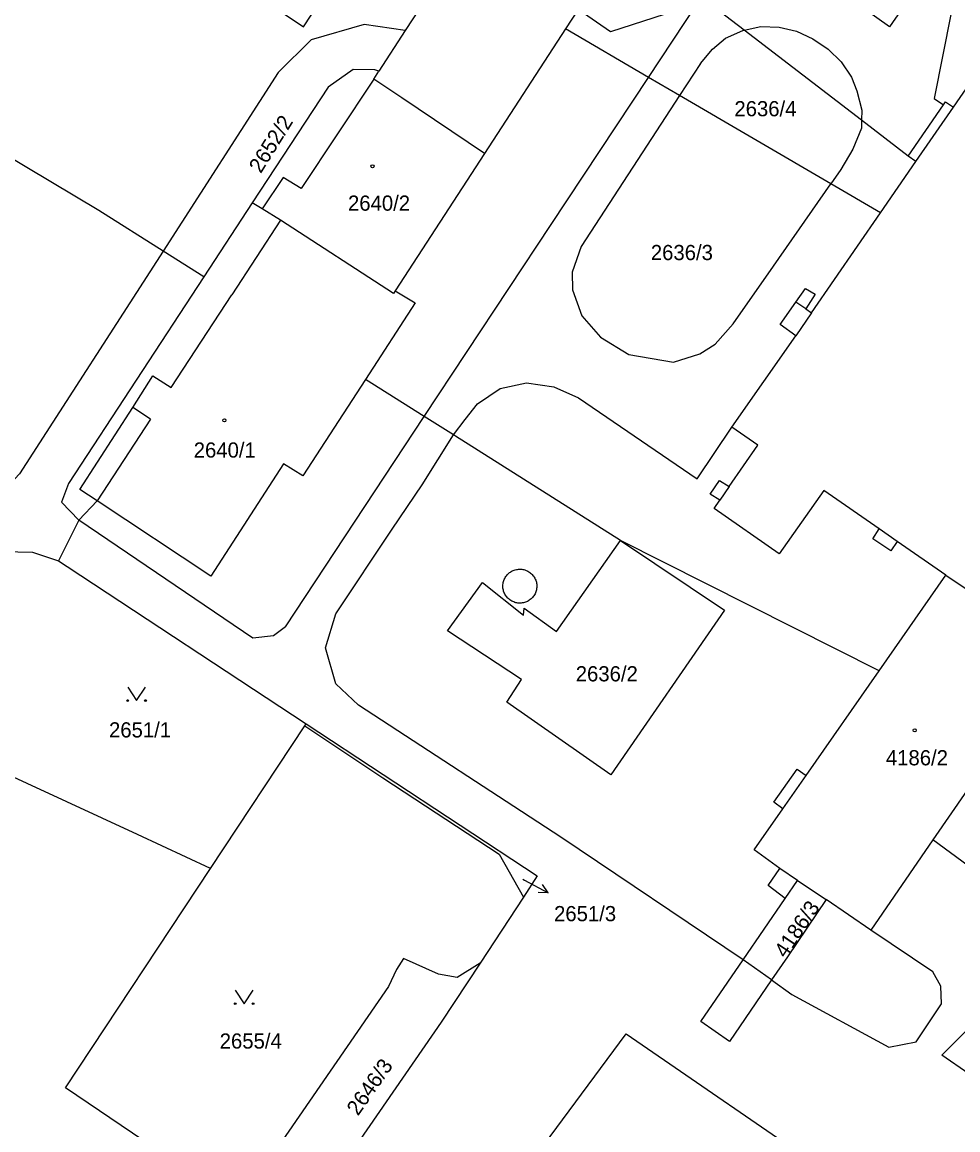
# Model space of a CAD drawing. Extents: x -527335 to -526256, y -1079142 to -1077809.
# Drawn here: x -527132.2 to -527027.3, y -1078723.7 to -1078599.7 of the extents above; entities that cross this region are included whole.
import ezdxf

# ---------------------------------------------------------------- set-up
doc = ezdxf.new("R2010")
doc.units = 0
for name, color, linetype in [('Vrstva 1', 7, 'Continuous'), ('Vrstva 2', 7, 'Continuous'), ('Vrstva 3', 7, 'Continuous'), ('Vrstva 4', 7, 'Continuous'), ('Vrstva 5', 7, 'Continuous'), ('Vrstva 7', 7, 'Continuous')]:
    doc.layers.add(name, color=color, linetype=linetype)

msp = doc.modelspace()

# ---------------------------------------------------------------- linework, layer by layer
at = {"layer": 'Vrstva 1'}
for p, q in [((-527084.24, -1078592.92), (-527089.24, -1078600.63)), ((-527069.88, -1078598.28), (-527071.3, -1078600.46)), ((-527089.24, -1078600.63), (-527092.19, -1078605.19)), ((-527071.3, -1078600.46), (-527080.35, -1078614.41)), ((-527080.35, -1078614.41), (-527090.38, -1078629.79)), ((-527106.37, -1078619.93), (-527111.8, -1078628.22)), ((-527111.8, -1078628.22), (-527116.37, -1078625.34)), ((-527125.8, -1078655.47), (-527128.08, -1078659.99)), ((-527036.17, -1078672.32), (-527028.7, -1078661.6)), ((-527111.05, -1078694.45), (-527100.48, -1078678.48)), ((-527100.48, -1078678.48), (-527100.33, -1078678.25)), ((-527076, -1078697.64), (-527080.84, -1078705.04))]:
    msp.add_line(p, q, dxfattribs=at)
for points in [[(-527032.9, -1078614.69), (-527028.96, -1078608.95), (-527028.74, -1078608.62), (-527027.84, -1078609.21), (-527013.93, -1078589.06), (-527018.97, -1078585.47), (-527022.71, -1078582.8), (-527034.32, -1078599.25), (-527035, -1078600.21), (-527045.31, -1078592.89), (-527044.64, -1078591.95), (-527045.34, -1078591.68), (-527030.72, -1078570.54), (-527019.5, -1078578.37), (-527020.66, -1078580.03), (-527011.71, -1078586.28), (-527007.77, -1078580.59), (-526958.39, -1078614.81), (-526968.02, -1078629.02)], [(-527116.37, -1078625.34), (-527123.55, -1078620.8), (-527150.28, -1078604.87), (-527192.47, -1078579.74), (-527193.56, -1078579.08), (-527199.41, -1078575.6)], [(-527097.46, -1078584.88), (-527105.59, -1078596.9), (-527101.78, -1078599.46), (-527100.62, -1078600.24), (-527092.63, -1078588.02)], [(-527055.53, -1078597.34), (-527056.53, -1078597.66), (-527066.26, -1078600.79), (-527069.88, -1078598.28)], [(-527032.9, -1078614.69), (-527038.13, -1078610.68), (-527051.29, -1078600.6), (-527055.53, -1078597.34)], [(-527089.24, -1078600.63), (-527093.84, -1078599.97), (-527099.76, -1078601.69), (-527103.47, -1078605.35), (-527116.37, -1078625.34)], [(-527036.02, -1078621.06), (-527041.58, -1078617.81), (-527058.52, -1078607.92), (-527061.99, -1078605.89), (-527071.3, -1078600.46)], [(-527092.19, -1078605.19), (-527092.64, -1078605.04), (-527095.07, -1078605), (-527097.88, -1078606.99), (-527106.37, -1078619.93)], [(-527080.35, -1078614.41), (-527089.62, -1078608.18), (-527092.76, -1078606.07), (-527092.19, -1078605.19)], [(-527036.02, -1078621.06), (-527032.04, -1078615.3), (-527032.9, -1078614.69)], [(-527090.38, -1078629.79), (-527090.57, -1078630.08), (-527103.21, -1078621.85), (-527105.25, -1078620.61), (-527106.37, -1078619.93)], [(-527028.7, -1078661.6), (-527034.13, -1078657.85), (-527034.83, -1078658.88), (-527036.85, -1078657.54), (-527036.16, -1078656.44), (-527042.37, -1078652.15), (-527047.34, -1078659.21), (-527054.65, -1078654.16), (-527054.01, -1078653.23), (-527055.07, -1078652.54), (-527054.02, -1078651.02), (-527052.95, -1078651.7), (-527049.75, -1078647.05), (-527052.66, -1078645.04), (-527045.47, -1078634.82), (-527047.26, -1078633.54), (-527045.49, -1078631.04), (-527044.4, -1078629.5), (-527043.32, -1078630.17), (-527044.38, -1078631.79), (-527043.73, -1078632.24), (-527036.02, -1078621.06)], [(-527116.37, -1078625.34), (-527132.46, -1078650.27), (-527134.42, -1078652.38), (-527137.13, -1078653.92), (-527149.78, -1078655.77), (-527159.8, -1078657.78), (-527171.17, -1078661.31), (-527177.71, -1078664.84), (-527183.15, -1078668.47), (-527187.88, -1078671.32), (-527192.11, -1078672.93), (-527195.71, -1078673.39), (-527199.46, -1078672.73), (-527204.98, -1078670.57), (-527228.94, -1078656.95), (-527235.73, -1078654.01), (-527239.42, -1078653.58), (-527242.39, -1078654.19), (-527245.02, -1078654.86), (-527247.81, -1078654.99), (-527253.05, -1078652.95)], [(-527111.8, -1078628.22), (-527126.96, -1078651.34), (-527127.75, -1078653.43), (-527125.8, -1078655.47)], [(-527090.38, -1078629.79), (-527088.13, -1078631.14), (-527093.68, -1078639.69)], [(-527093.68, -1078639.69), (-527100.7, -1078650.5), (-527102.88, -1078649.16), (-527111.02, -1078661.73), (-527123.73, -1078653.3), (-527125.8, -1078655.47)], [(-527036.17, -1078672.32), (-527065.11, -1078657.74), (-527083.61, -1078646.04), (-527083.83, -1078645.91), (-527087.11, -1078643.84), (-527093.68, -1078639.69)], [(-527065.11, -1078657.74), (-527053.48, -1078665.54), (-527066.21, -1078683.97), (-527077.86, -1078675.81), (-527076.2, -1078673.3), (-527084.51, -1078667.86), (-527080.6, -1078662.44), (-527076, -1078666.1), (-527075.9, -1078665.3), (-527072.3, -1078667.9), (-527065.11, -1078657.74)], [(-527165.78, -1078664.86), (-527157.95, -1078662.5), (-527148.99, -1078660.76), (-527136.01, -1078658.93), (-527130.99, -1078659.02), (-527128.08, -1078659.99)], [(-527128.08, -1078659.99), (-527127.09, -1078660.65), (-527100.33, -1078678.25)], [(-527028.7, -1078661.6), (-527015.73, -1078670.3), (-527014.76, -1078670.99)], [(-527111.05, -1078694.45), (-527119.22, -1078690.63), (-527139.54, -1078681.28), (-527147.37, -1078677.43), (-527153.14, -1078673.82), (-527165.78, -1078664.86)], [(-527046.7, -1078697.8), (-527048.58, -1078696.34), (-527047.28, -1078694.45), (-527050.15, -1078692.37), (-527046.94, -1078687.77), (-527047.97, -1078687.02), (-527045.34, -1078683.32), (-527044.33, -1078684.02), (-527036.17, -1078672.32)], [(-527100.48, -1078678.48), (-527091.74, -1078684.3), (-527078.73, -1078692.83), (-527076, -1078697.64)], [(-527100.33, -1078678.25), (-527074.45, -1078695.27), (-527076, -1078697.64)], [(-527015.39, -1078682.81), (-527024.2, -1078695.62), (-527030.14, -1078691.25), (-527037.08, -1078701.34), (-527042.08, -1078697.91)], [(-527022.2, -1078722.85), (-527024.62, -1078721.48), (-527026.17, -1078719.51), (-527026.1, -1078717.42), (-527029.13, -1078715.35), (-527002.95, -1078689.07), (-527015.39, -1078682.81)], [(-527100.64, -1078733.75), (-527102.25, -1078735.96), (-527127.31, -1078719.02), (-527111.05, -1078694.45)], [(-527046.7, -1078697.8), (-527045.3, -1078695.78), (-527042.08, -1078697.91)], [(-527042.08, -1078697.91), (-527046.44, -1078704.32), (-527048.22, -1078706.92), (-527052.91, -1078713.81), (-527056.12, -1078711.58), (-527051.4, -1078704.68), (-527046.7, -1078697.8)], [(-527080.84, -1078705.04), (-527083.41, -1078706.65), (-527085.52, -1078706.27), (-527089.43, -1078704.54), (-527090.21, -1078705.74), (-527091.13, -1078707.66), (-527103.45, -1078725.55), (-527097.86, -1078729.26), (-527100.64, -1078733.75)], [(-527080.84, -1078705.04), (-527085.2, -1078711.65), (-527097.53, -1078729.48)], [(-527083.63, -1078738.83), (-527064.48, -1078712.94), (-527041.46, -1078728.79), (-527037.96, -1078731.19)]]:
    msp.add_lwpolyline(points, dxfattribs=at)
at = {"layer": 'Vrstva 3'}
for points in [[(-527120.33, -1078674.15), (-527119.33, -1078675.65), (-527118.33, -1078674.15)], [(-527108.28, -1078708.08), (-527107.28, -1078709.58), (-527106.28, -1078708.08)]]:
    msp.add_lwpolyline(points, dxfattribs=at)
for centre in [(-527120.33, -1078675.65), (-527118.33, -1078675.65), (-527108.28, -1078709.58), (-527106.28, -1078709.58)]:
    msp.add_circle(centre, 0.1, dxfattribs=at)
at = {"layer": 'Vrstva 4'}
for p, q in [((-527061.99, -1078605.89), (-527056.53, -1078597.66)), ((-527028.09, -1078598.67), (-527030.01, -1078608.26)), ((-527053.36, -1078601.5), (-527051.41, -1078600.62)), ((-527051.41, -1078600.62), (-527051.29, -1078600.6)), ((-527051.29, -1078600.6), (-527049.42, -1078600.2)), ((-527049.42, -1078600.2), (-527047.35, -1078600.28)), ((-527047.35, -1078600.28), (-527045.41, -1078600.71)), ((-527045.41, -1078600.71), (-527043.57, -1078601.57)), ((-527054.84, -1078602.73), (-527053.36, -1078601.5)), ((-527043.57, -1078601.57), (-527041.87, -1078602.71)), ((-527056.18, -1078604.33), (-527054.84, -1078602.73)), ((-527041.87, -1078602.71), (-527040.4, -1078604.14)), ((-527056.18, -1078604.33), (-527058.52, -1078607.92)), ((-527040.4, -1078604.14), (-527039.27, -1078605.86)), ((-527039.27, -1078605.86), (-527038.67, -1078607.4)), ((-527092.76, -1078606.07), (-527100.9, -1078618.33)), ((-527072.91, -1078622.34), (-527061.99, -1078605.89)), ((-527058.52, -1078607.92), (-527069.52, -1078624.8)), ((-527038.67, -1078607.4), (-527038.11, -1078609.54)), ((-527030.01, -1078608.26), (-527028.96, -1078608.95)), ((-527038.11, -1078609.54), (-527038.13, -1078610.68)), ((-527032.04, -1078615.3), (-527027.84, -1078609.21)), ((-527038.13, -1078610.68), (-527038.14, -1078611.58)), ((-527038.14, -1078611.58), (-527039.1, -1078613.91)), ((-527039.1, -1078613.91), (-527040.45, -1078616.19)), ((-527040.45, -1078616.19), (-527041.58, -1078617.81)), ((-527102.93, -1078617.08), (-527105.25, -1078620.61)), ((-527100.9, -1078618.33), (-527102.93, -1078617.08)), ((-527047.98, -1078627), (-527041.58, -1078617.81)), ((-527103.21, -1078621.85), (-527108.68, -1078630.21)), ((-527087.11, -1078643.84), (-527072.91, -1078622.34)), ((-527069.52, -1078624.8), (-527070.53, -1078627.68)), ((-527070.53, -1078627.68), (-527070.5, -1078629.68)), ((-527052.51, -1078633.49), (-527047.98, -1078627)), ((-527115.47, -1078640.6), (-527108.68, -1078630.21)), ((-527070.5, -1078629.68), (-527069.45, -1078632.56)), ((-527044.38, -1078631.79), (-527045.49, -1078631.04)), ((-527069.45, -1078632.56), (-527067.37, -1078634.98)), ((-527043.73, -1078632.24), (-527045.47, -1078634.82)), ((-527054.54, -1078635.74), (-527052.51, -1078633.49)), ((-527067.37, -1078634.98), (-527064.19, -1078636.89)), ((-527059.19, -1078637.78), (-527056.26, -1078636.85)), ((-527056.26, -1078636.85), (-527054.54, -1078635.74)), ((-527064.19, -1078636.89), (-527059.19, -1078637.78)), ((-527119.77, -1078642.84), (-527117.5, -1078639.31)), ((-527117.5, -1078639.31), (-527115.47, -1078640.6)), ((-527078.62, -1078640.73), (-527075.65, -1078640.07)), ((-527075.65, -1078640.07), (-527072.61, -1078640.52)), ((-527072.61, -1078640.52), (-527069.83, -1078641.75)), ((-527081.14, -1078642.44), (-527078.62, -1078640.73)), ((-527069.83, -1078641.75), (-527056.54, -1078650.84)), ((-527125.67, -1078652.01), (-527119.77, -1078642.84)), ((-527117.77, -1078644.13), (-527119.77, -1078642.84)), ((-527082.52, -1078644.19), (-527081.14, -1078642.44)), ((-527117.77, -1078644.13), (-527123.73, -1078653.3)), ((-527102.65, -1078667.38), (-527087.11, -1078643.84)), ((-527083.83, -1078645.91), (-527082.52, -1078644.19)), ((-527056.54, -1078650.84), (-527052.66, -1078645.04)), ((-527087.34, -1078651.48), (-527083.83, -1078645.91)), ((-527090.69, -1078656.47), (-527087.34, -1078651.48)), ((-527052.95, -1078651.7), (-527054.01, -1078653.23)), ((-527123.73, -1078653.3), (-527125.67, -1078652.01)), ((-527106.3, -1078668.65), (-527125.8, -1078655.47)), ((-527097.03, -1078665.93), (-527090.69, -1078656.47)), ((-527034.13, -1078657.85), (-527036.16, -1078656.44)), ((-527098.17, -1078669.75), (-527097.03, -1078665.93)), ((-527102.65, -1078667.38), (-527104, -1078668.4)), ((-527104, -1078668.4), (-527106.3, -1078668.65)), ((-527097, -1078673.79), (-527098.17, -1078669.75)), ((-527015.73, -1078670.3), (-527030.14, -1078691.25)), ((-527094.47, -1078676.17), (-527097, -1078673.79)), ((-527071.8, -1078690.93), (-527094.47, -1078676.17)), ((-527046.94, -1078687.77), (-527044.33, -1078684.02)), ((-527051.4, -1078704.68), (-527071.8, -1078690.93)), ((-527045.3, -1078695.78), (-527047.28, -1078694.45)), ((-527030.14, -1078706.02), (-527037.08, -1078701.34)), ((-527048.22, -1078706.92), (-527051.4, -1078704.68)), ((-527029.26, -1078707.61), (-527030.14, -1078706.02)), ((-527048.22, -1078706.92), (-527045.92, -1078708.54)), ((-527045.92, -1078708.54), (-527035.09, -1078714.45)), ((-527029.16, -1078709.61), (-527029.26, -1078707.61)), ((-527032, -1078713.85), (-527029.16, -1078709.61)), ((-527035.09, -1078714.45), (-527032, -1078713.85))]:
    msp.add_line(p, q, dxfattribs=at)
for points in [[(-527077.79, -1078664.14), (-527077.87, -1078664.05), (-527077.95, -1078663.95), (-527078.01, -1078663.85), (-527078.07, -1078663.75), (-527078.13, -1078663.64), (-527078.18, -1078663.52), (-527078.22, -1078663.41), (-527078.25, -1078663.29), (-527078.27, -1078663.17), (-527078.29, -1078663.05), (-527078.3, -1078662.93), (-527078.3, -1078662.81), (-527078.3, -1078662.69), (-527078.28, -1078662.56), (-527078.26, -1078662.44), (-527078.23, -1078662.32), (-527078.2, -1078662.21), (-527078.15, -1078662.09), (-527078.1, -1078661.99), (-527078.04, -1078661.88), (-527077.98, -1078661.77), (-527077.91, -1078661.68), (-527077.83, -1078661.58), (-527077.74, -1078661.49), (-527077.66, -1078661.41), (-527077.56, -1078661.33), (-527077.46, -1078661.26), (-527077.36, -1078661.2), (-527077.25, -1078661.14), (-527077.14, -1078661.09), (-527077.03, -1078661.04), (-527076.91, -1078661.01), (-527076.79, -1078660.98), (-527076.67, -1078660.96), (-527076.55, -1078660.94), (-527076.43, -1078660.94), (-527076.31, -1078660.94), (-527076.18, -1078660.95), (-527076.06, -1078660.97), (-527075.94, -1078660.99), (-527075.83, -1078661.02), (-527075.71, -1078661.07), (-527075.6, -1078661.11), (-527075.49, -1078661.17), (-527075.39, -1078661.23), (-527075.28, -1078661.3), (-527075.19, -1078661.37), (-527075.1, -1078661.45), (-527075.01, -1078661.54)], [(-527075.01, -1078661.54), (-527074.93, -1078661.63), (-527074.85, -1078661.73), (-527074.79, -1078661.83), (-527074.73, -1078661.94), (-527074.67, -1078662.04), (-527074.62, -1078662.16), (-527074.58, -1078662.27), (-527074.55, -1078662.39), (-527074.53, -1078662.51), (-527074.51, -1078662.63), (-527074.5, -1078662.75), (-527074.5, -1078662.87), (-527074.5, -1078663), (-527074.52, -1078663.12), (-527074.54, -1078663.24), (-527074.57, -1078663.35), (-527074.6, -1078663.47), (-527074.65, -1078663.58), (-527074.7, -1078663.7), (-527074.76, -1078663.8), (-527074.82, -1078663.91), (-527074.9, -1078664.01), (-527074.97, -1078664.1), (-527075.06, -1078664.19), (-527075.15, -1078664.27), (-527075.24, -1078664.35), (-527075.34, -1078664.42), (-527075.44, -1078664.48), (-527075.55, -1078664.54), (-527075.66, -1078664.59), (-527075.77, -1078664.64), (-527075.89, -1078664.67), (-527076.01, -1078664.7), (-527076.13, -1078664.72), (-527076.25, -1078664.74), (-527076.37, -1078664.74), (-527076.49, -1078664.74), (-527076.62, -1078664.73), (-527076.74, -1078664.71), (-527076.86, -1078664.69), (-527076.97, -1078664.66), (-527077.09, -1078664.61), (-527077.2, -1078664.57), (-527077.31, -1078664.51), (-527077.42, -1078664.45), (-527077.52, -1078664.38), (-527077.61, -1078664.31), (-527077.7, -1078664.23), (-527077.79, -1078664.14)]]:
    msp.add_lwpolyline(points, dxfattribs=at)
at = {"layer": 'Vrstva 5'}
for centre in [(-527092.91, -1078615.84), (-527109.5, -1078644.27), (-527032.17, -1078678.97)]:
    msp.add_circle(centre, 0.175, dxfattribs=at)
at = {"layer": 'Vrstva 7'}
for p, q in [((-527076.07, -1078695.64), (-527075.87, -1078695.75)), ((-527075.87, -1078695.75), (-527073.22, -1078697.16)), ((-527073.22, -1078697.16), (-527073.87, -1078696.25)), ((-527073.22, -1078697.16), (-527074.34, -1078697.13))]:
    msp.add_line(p, q, dxfattribs=at)

# ---------------------------------------------------------------- texts
at = {"layer": 'Vrstva 2'}
for s, p in [('2636/4', (-527052.37, -1078610.24)), ('2640/2', (-527095.65, -1078620.81)), ('2636/3', (-527061.73, -1078626.34)), ('2640/1', (-527112.93, -1078648.45)), ('2636/2', (-527070.14, -1078673.5)), ('2651/1', (-527122.42, -1078679.78)), ('4186/2', (-527035.4, -1078682.9)), ('2651/3', (-527072.57, -1078700.35)), ('2655/4', (-527110.02, -1078714.61))]:
    msp.add_text(s, height=1.7, dxfattribs=at).set_placement(p)
for s, rotation, p in [('2652/2', 58, (-527105.42, -1078616.72)), ('4186/3', 56, (-527046.62, -1078704.57)), ('2646/3', 55, (-527094.53, -1078722.22))]:
    msp.add_text(s, height=1.7, rotation=rotation, dxfattribs=at).set_placement(p)

doc.saveas('drawing.dxf')
